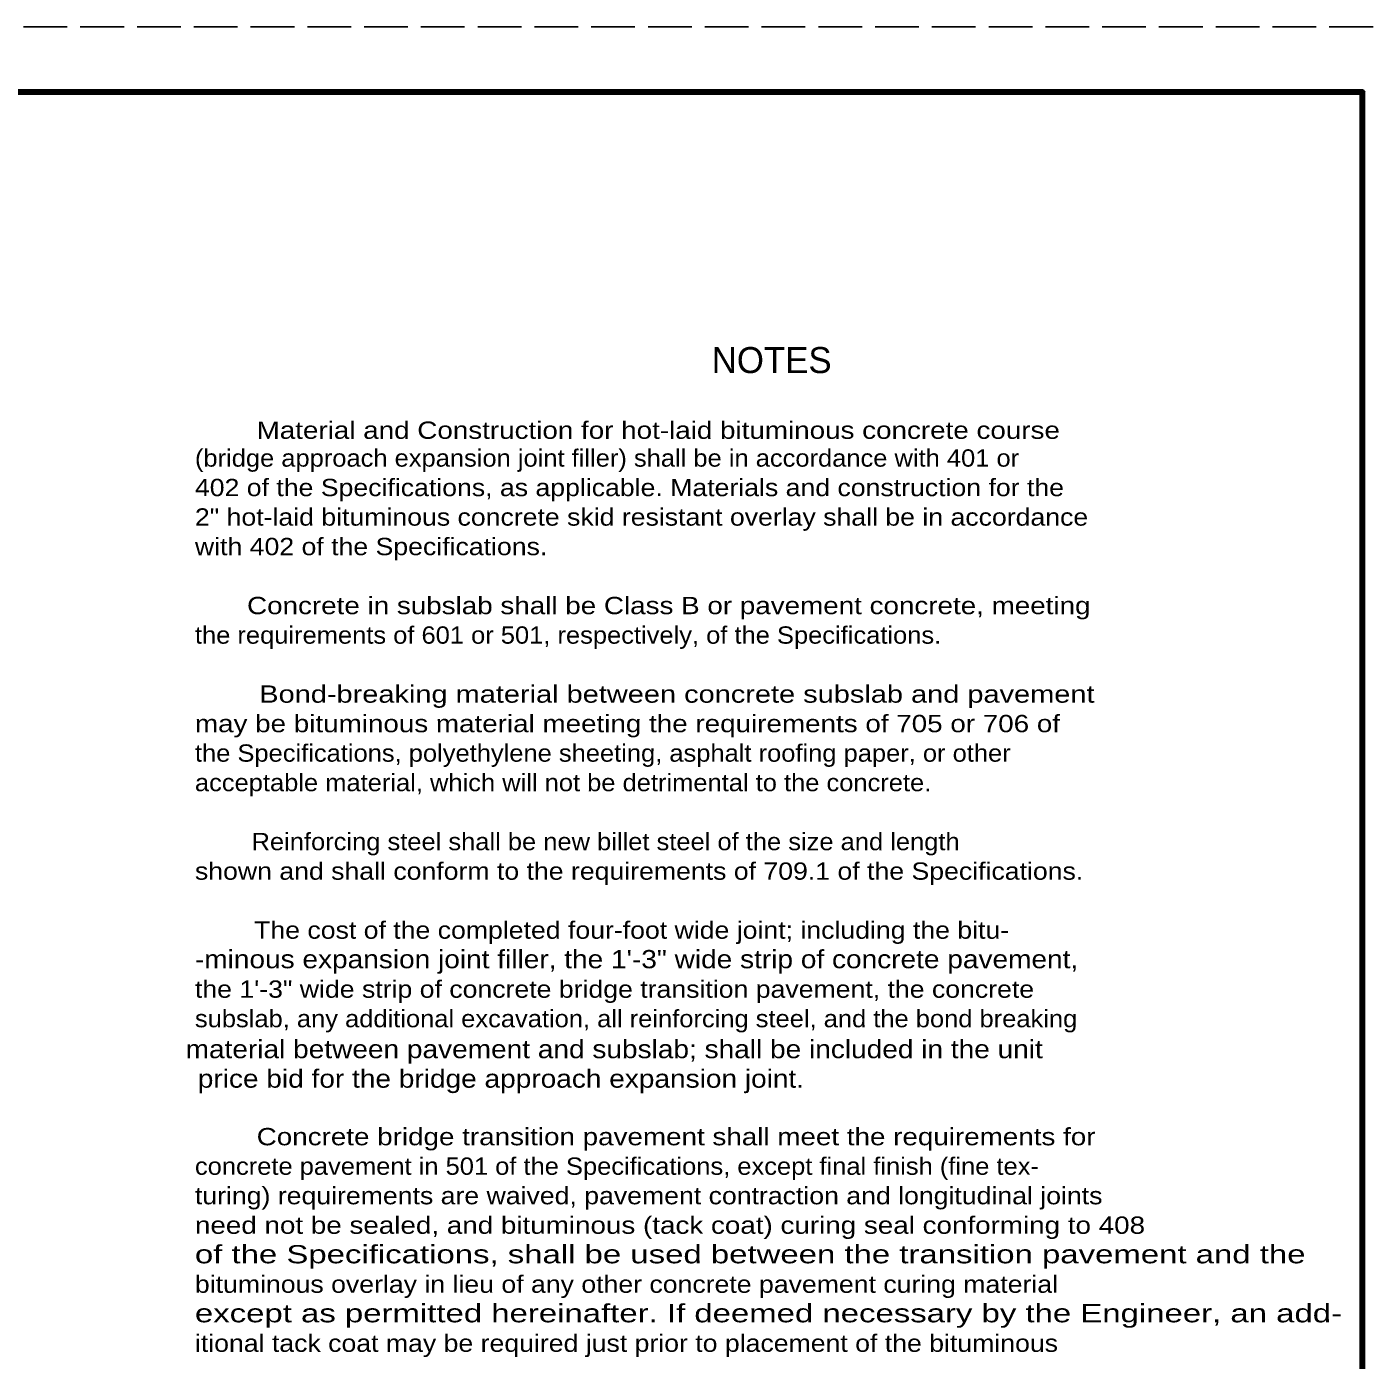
# Model space of a CAD drawing. Extents: x 36.4 to 71.7, y 0.5 to 22.5.
# Drawn here: x 61.26 to 71.6, y 12.24 to 22.48 of the extents above; entities that cross this region are included whole.
import ezdxf

# ---------------------------------------------------------------- set-up
doc = ezdxf.new("R2010")
doc.units = 0
doc.header["$LTSCALE"] = 0.056
doc.header["$PDMODE"] = 32
doc.header["$PDSIZE"] = 0.028
doc.linetypes.add('LONG_DASHED', pattern=[7.5, 6, -1.5])
doc.layers.add('1', color=7, linetype='Continuous', lineweight=40)
doc.layers.add('3', color=7, linetype='Continuous', lineweight=13)

msp = doc.modelspace()

# ---------------------------------------------------------------- linework, layer by layer
at = {"layer": '1', "linetype": 'LONG_DASHED', "lineweight": 25}
msp.add_line((71.60142, 22.47742), (36.40142, 22.47742), dxfattribs=at)
at = {"layer": '1', "lineweight": 158}
msp.add_line((71.51808, 21.97742), (39.01808, 21.97742), dxfattribs=at)
msp.add_lwpolyline([(71.51808, 21.97742), (71.51808, 0.97742), (39.01808, 0.97742)], dxfattribs=at)
at = {"layer": '1'}
msp.add_point((71.51808, 21.97742), dxfattribs=at)

# ---------------------------------------------------------------- texts
at = {"layer": '3'}
msp.add_text('NOTES', height=0.2, dxfattribs=at).set_placement((66.52242, 19.81817))
for s, height, width, p in [('        Material and Construction for hot-laid bituminous concrete course', 0.133, 1.2, (62.5535, 19.313)), ('(bridge approach expansion joint filler) shall be in accordance with 401 or', 0.133, 1.1, (62.55408, 19.09925)), ('402 of the Specifications, as applicable. Materials and construction for the', 0.133, 1.15, (62.55408, 18.87267)), ('2" hot-laid bituminous concrete skid resistant overlay shall be in accordance', 0.133, 1.15, (62.55408, 18.646)), ('with 402 of the Specifications.', 0.133, 1.15, (62.55408, 18.41925)), ('        Concrete in subslab shall be Class B or pavement concrete, meeting', 0.133, 1.2, (62.47992, 17.966)), ('the requirements of 601 or 501, respectively, of the Specifications.', 0.133, 1.1, (62.55408, 17.73925)), ('        Bond-breaking material between concrete subslab and pavement', 0.133, 1.25, (62.55408, 17.286)), ('may be bituminous material meeting the requirements of 705 or 706 of', 0.133, 1.2, (62.55408, 17.05925)), ('the Specifications, polyethylene sheeting, asphalt roofing paper, or other', 0.133, 1.1, (62.55408, 16.83267)), ('acceptable material, which will not be detrimental to the concrete.', 0.133, 1.1, (62.55408, 16.606)), ('        Reinforcing steel shall be new billet steel of the size and length', 0.133, 1.1, (62.55408, 16.15267)), ('shown and shall conform to the requirements of 709.1 of the Specifications.', 0.133, 1.15, (62.55408, 15.926)), ('        The cost of the completed four-foot wide joint; including the bitu-', 0.133, 1.15, (62.55408, 15.47267)), ('-minous expansion joint filler, the 1\'-3" wide strip of concrete pavement,', 0.14, 1.15, (62.55408, 15.246)), ('the 1\'-3" wide strip of concrete bridge transition pavement, the concrete', 0.133, 1.15, (62.55408, 15.01925)), ('subslab, any additional excavation, all reinforcing steel, and the bond breaking', 0.133, 1.1, (62.55408, 14.79267)), (' material between pavement and subslab; shall be included in the unit', 0.14, 1.15, (62.42275, 14.55508)), ('price bid for the bridge approach expansion joint.', 0.14, 1.15, (62.576, 14.32833)), ('        Concrete bridge transition pavement shall meet the requirements for', 0.133, 1.2, (62.55408, 13.886)), ('concrete pavement in 501 of the Specifications, except final finish (fine tex-', 0.133, 1.1, (62.55408, 13.65925)), ('turing) requirements are waived, pavement contraction and longitudinal joints', 0.133, 1.15, (62.55408, 13.43267)), ('need not be sealed, and bituminous (tack coat) curing seal conforming to 408', 0.133, 1.2, (62.55408, 13.206)), ('of the Specifications, shall be used between the transition pavement and the', 0.14, 1.35, (62.55408, 12.97925)), ('bituminous overlay in lieu of any other concrete pavement curing material', 0.133, 1.15, (62.55408, 12.75267)), ('except as permitted hereinafter. If deemed necessary by the Engineer, an add-', 0.14, 1.35, (62.55408, 12.526)), ('itional tack coat may be required just prior to placement of the bituminous', 0.133, 1.15, (62.55408, 12.29925))]:
    msp.add_text(s, height=height, dxfattribs=dict(at, width=width)).set_placement(p)

doc.saveas('drawing.dxf')
